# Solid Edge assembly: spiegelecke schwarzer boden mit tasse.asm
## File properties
Author: Dieter
Template: Normal.asm
Last saved by: Dieter
Revision: 4
Application: Solid Edge
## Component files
Spiegelecke Boden schwarz.par
Tasse.par
